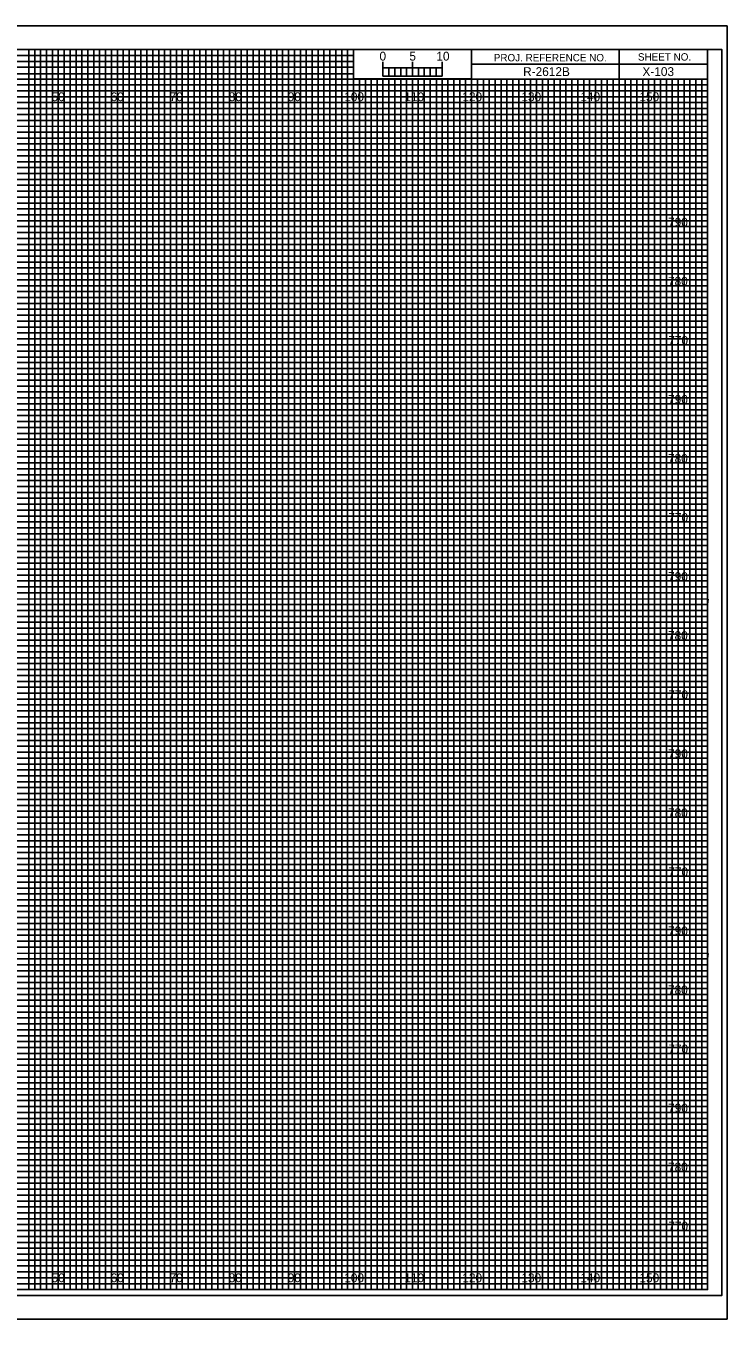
# Model space of a CAD drawing. Extents: x -13 to 323, y -5 to 214.
# Drawn here: x 204.5 to 323.3, y -5 to 214 of the extents above; entities that cross this region are included whole.
import ezdxf

# ---------------------------------------------------------------- set-up
doc = ezdxf.new("R2010")
doc.units = 0
for name, color, linetype in [('Prop XS Bar Scale Labels', 7, 'Continuous'), ('Prop XS Elevation Labels', 7, 'Continuous'), ('Prop XS Offset Labels', 7, 'Continuous'), ('Prop XS Project Number', 7, 'Continuous'), ('Prop XS Sheet Number', 7, 'Continuous'), ('Sheet Cross Section CELL', 7, 'Continuous'), ('Sheet Cross Section Grid Major CELL', 7, 'Continuous'), ('Sheet Cross Section Grid Middle CELL', 7, 'Continuous'), ('Sheet Cross Section Grid Minor 1 CELL', 7, 'Continuous'), ('Sheet Cross Section Grid Minor 2 CELL', 7, 'Continuous'), ('Sheet Cross Section Scale CELL', 7, 'Continuous'), ('Sheet Cutting Line CELL', 7, 'Continuous'), ('Sheet DOT Grid CELL', 7, 'Continuous'), ('Sheet Plot Border Inside CELL', 7, 'Continuous'), ('Sheet Plot Border Outside CELL', 7, 'Continuous')]:
    doc.layers.add(name, color=color, linetype=linetype)

msp = doc.modelspace()

# ---------------------------------------------------------------- linework, layer by layer
at = {"layer": 'Sheet Cross Section CELL'}
for p, q in [((305, 210), (305, 205)), ((305, 205), (305, 210)), ((280, 207.5), (280, 205)), ((320, 207.49), (280, 207.49)), ((280, 205), (320, 205))]:
    msp.add_line(p, q, dxfattribs=at)
for points in [[(320, 210), (0, 210), (0, 0), (320, 0)], [(280, 210), (260, 210), (260, 205.03), (280, 205.03)], [(320, 210), (280, 210), (280, 205), (320, 205)]]:
    msp.add_lwpolyline(points, close=True, dxfattribs=at)
at = {"layer": 'Sheet Cross Section Grid Major CELL'}
for p, q in [((210, 210), (200, 210)), ((210, 0), (210, 210)), ((230, 210), (220, 210)), ((220, 210), (220, 0)), ((230, 0), (230, 210)), ((250, 210), (240, 210)), ((240, 210), (240, 0)), ((250, 0), (250, 210)), ((260, 210), (260, 0)), ((270, 0), (270, 205)), ((290, 205), (280, 205)), ((280, 205), (280, 0)), ((290, 0), (290, 205)), ((310, 205), (300, 205)), ((300, 205), (300, 0)), ((310, 0), (310, 205)), ((220, 0), (210, 0)), ((240, 0), (230, 0)), ((260, 0), (250, 0)), ((280, 0), (270, 0)), ((300, 0), (290, 0)), ((320, 0), (310, 0)), ((320, 0), (320, 0))]:
    msp.add_line(p, q, dxfattribs=at)
for points in [[(0, 200), (320, 200), (320, 190), (0, 190)], [(0, 180), (320, 180), (320, 170), (0, 170)], [(0, 160), (320, 160), (320, 150), (0, 150)], [(0, 140), (320, 140), (320, 130), (0, 130)], [(0, 120), (320, 120), (320, 110), (0, 110)], [(0, 100), (320, 100), (320, 90), (0, 90)], [(0, 80), (320, 80), (320, 70), (0, 70)], [(0, 60), (320, 60), (320, 50), (0, 50)], [(0, 40), (320, 40), (320, 30), (0, 30)], [(0, 20), (320, 20), (320, 10), (0, 10)]]:
    msp.add_lwpolyline(points, dxfattribs=at)
at = {"layer": 'Sheet Cross Section Grid Middle CELL'}
for points in [[(195, 210), (205, 210), (205, 0), (215, 0), (215, 210), (225, 210), (225, 0), (235, 0), (235, 210), (245, 210), (245, 0), (255, 0), (255, 210), (259.93, 210), (260, 210), (260, 205), (264.99, 205), (264.99, 0), (275, 0), (275, 205), (285, 205), (285, 0), (295, 0), (295, 205), (305, 205), (305, 0), (315, 0), (315, 205)], [(0, 205), (275, 205)], [(0, 185), (320, 185), (320, 195), (0, 195)], [(0, 165), (320, 165), (320, 175), (0, 175)], [(0, 145), (320, 145), (320, 155), (0, 155)], [(0, 125), (320, 125), (320, 135), (0, 135)], [(0, 105), (320, 105), (320, 115), (0, 115)], [(0, 85), (320, 85), (320, 95), (0, 95)], [(0, 65), (320, 65), (320, 75), (0, 75)], [(0, 45), (320, 45), (320, 55), (0, 55)], [(0, 25), (320, 25), (320, 35), (0, 35)], [(0, 5), (320, 5), (320, 15), (0, 15)]]:
    msp.add_lwpolyline(points, dxfattribs=at)
at = {"layer": 'Sheet Cross Section Grid Minor 1 CELL'}
for p, q in [((0, 209), (260, 209)), ((260, 209), (260, 207.98)), ((260, 207.98), (0, 207.98)), ((0, 207), (260, 207)), ((260, 205.89), (0, 205.89)), ((260, 207), (260, 205.89)), ((0, 204), (320, 204))]:
    msp.add_line(p, q, dxfattribs=at)
for points in [[(0, 203), (270, 203), (320, 203), (320, 202), (0, 202)], [(0, 201), (320, 201), (320, 199), (0, 199)], [(0, 198), (320, 198), (320, 197), (0, 196.98)], [(0, 196), (320, 196), (320, 194), (0, 194)], [(0, 193), (320, 193), (320, 192), (0, 192)], [(0, 191), (320, 191), (320, 189), (0, 189)], [(0, 188), (320, 188), (320, 187), (0, 187)], [(0, 186), (320, 186), (320, 184), (0, 184)], [(0, 183), (320, 183), (320, 182), (0, 182)], [(0, 181), (320, 181), (320, 179), (0, 179)], [(0, 178), (320, 178), (320, 177), (0, 177)], [(0, 176), (320, 176), (320, 173.95), (320, 173), (320, 172), (0, 172)], [(0, 174), (320, 174), (320, 173), (0, 173)], [(0, 171), (320, 171), (320, 169), (0, 169.03)], [(0, 169.03), (320, 169), (320, 168), (0, 168)], [(0, 167), (320, 167), (320, 166), (0, 166)], [(0, 164), (320, 164), (320, 163), (0, 163)], [(0, 162), (320, 162), (320, 161), (0, 161)], [(-0.07, 158.89), (320, 158.89), (320, 157.88), (-0.07, 157.88)], [(0, 157), (320, 157), (320, 156), (0, 156)], [(0, 154), (320, 154), (320, 153), (0, 153)], [(0, 152), (320, 152), (320, 151), (0, 151)], [(0, 149), (320, 149), (320, 148), (0, 148)], [(0, 147), (320, 147), (320, 146), (0, 146)], [(0, 144), (320, 144), (320, 143), (0, 143)], [(0, 142), (320, 142), (320, 141), (0, 141)], [(0, 139), (320, 139), (319.99, 137.98), (0, 138)], [(0, 137), (320, 137), (320, 136), (0, 136)], [(0, 134), (320, 134), (320, 133), (0, 133)], [(0, 132), (320, 132), (320, 131), (0, 131)], [(0, 129), (320, 129), (320, 128), (0, 128)], [(0, 127), (320, 127), (320, 126), (0, 126)], [(0, 124), (320, 124), (320, 123), (0, 123)], [(0, 122), (320, 122), (320, 121), (0, 121)], [(0, 119), (320, 119), (320, 118), (0, 118)], [(0, 116.99), (320.07, 116.91), (320, 116), (0, 116)], [(0, 114), (320, 114), (320, 113), (0, 113)], [(0, 112), (320, 112), (320, 111), (0, 111)], [(0, 109), (320, 109), (320, 108), (0, 108)], [(0, 107), (320, 107), (320, 106), (0, 106)], [(0, 104), (320, 104), (320, 103), (0, 103)], [(0, 102), (320, 102), (320, 101), (0, 101)], [(0, 99), (320, 99), (320, 98), (0, 98)], [(0, 97), (320, 97), (320, 96), (0, 96)], [(0, 94), (320, 94), (320, 93), (0, 93)], [(0, 92), (320, 92), (320, 91), (0, 91)], [(0, 89), (320, 89), (320, 88), (0, 88)], [(0, 87), (320, 87), (320, 86), (0, 86)], [(0, 84), (320, 84), (320, 83), (0, 83)], [(0, 82), (320, 82), (320, 81), (0, 81)], [(0, 79), (320, 79), (319.99, 77.98), (0, 78)], [(0, 77), (320, 77), (320, 76), (0, 76)], [(0, 74), (320, 74), (320, 73), (0, 73)], [(0, 72), (320, 72), (320, 71), (0, 71)], [(0, 69), (320, 69), (320, 68), (0, 68)], [(0, 67), (320, 67), (320, 66), (0, 66)], [(0, 64), (320, 64), (320, 63), (0, 63)], [(0, 62), (320, 62), (320, 61), (0, 61)], [(0, 59), (320, 59), (320, 58), (0, 58)], [(0, 56.99), (320.07, 56.91), (320, 56), (0, 56)], [(0, 54), (320, 54), (320, 53), (0, 53)], [(0, 52), (320, 52), (320, 51), (0, 51)], [(0, 49), (320, 49), (320, 48), (0, 48)], [(0, 47), (320, 47), (320, 46), (0, 46)], [(0, 44), (320, 44), (320, 43), (0, 43)], [(0, 42), (320, 42), (320, 41), (0, 41)], [(0, 39), (320, 39), (320, 38), (0, 38)], [(0, 37), (320, 37), (320, 36), (0, 36)], [(0, 34), (320, 34), (320, 33), (0, 33)], [(0, 32), (320, 32), (320, 31), (0, 31)], [(0, 29), (320, 29), (320, 28), (0, 28)], [(0, 27), (320, 27), (320, 26), (0, 26)], [(0, 24), (320, 24), (320, 23), (0, 23)], [(0, 22), (320, 22), (320, 21), (0, 21)], [(0, 19), (320, 19), (320, 18), (0, 18)], [(0, 17), (320, 17), (320, 16), (0, 16)], [(0, 14), (320, 14), (320, 13), (0, 13)], [(0, 12), (320, 12), (320, 11), (0, 11)], [(0, 9), (320, 9), (320, 8), (0, 8)], [(0, 7), (320, 7), (320, 6), (0, 6)], [(0, 4), (320, 4), (320, 3), (0, 3)], [(0, 2), (320, 2), (320, 1), (0, 1)]]:
    msp.add_lwpolyline(points, dxfattribs=at)
at = {"layer": 'Sheet Cross Section Grid Minor 2 CELL'}
for p, q in [((267, 205), (266.01, 205)), ((266.01, 205), (266.01, 0)), ((267, 0), (267, 205)), ((269, 205), (268, 205)), ((268, 205), (268, 0)), ((269, 0), (269, 205)), ((266.01, 0), (265, 0)), ((268, 0), (267, 0))]:
    msp.add_line(p, q, dxfattribs=at)
for points in [[(205, 0), (206, 0), (206, 210), (207, 210), (207, 0)], [(207, 0), (208, 0), (208, 210), (209, 210), (209, 0)], [(210, 0), (211, 0), (211, 210), (212, 210), (212, 0)], [(212, 0), (213, 0), (213, 210), (214, 210), (214, 0)], [(215, 0), (216, 0), (216, 210), (217, 210), (217, 0)], [(217, 0), (218, 0), (218, 210), (219, 210), (219, 0)], [(220, 0), (221, 0), (221, 210), (222, 210), (222, 0)], [(222, 0), (223, 0), (223, 210), (224, 210), (224, 0)], [(225, 0), (226, 0), (226, 210), (227, 210), (227, 0)], [(227, 0), (228, 0), (228, 210), (229, 210), (229, 0)], [(230, 0), (231, 0), (231, 210), (232, 210), (232, 0)], [(232, 0), (233, 0), (233, 210), (234, 210), (234, 0)], [(235, 0), (236, 0), (236, 210), (237, 210), (237, 0)], [(237, 0), (238, 0), (238, 210), (239, 210), (239, 0)], [(240, 0), (241, 0), (241, 210), (242, 210), (242, 0)], [(242, 0), (243, 0), (243, 210), (244, 210), (244, 0)], [(245, 0), (246, 0), (246, 210), (247, 210), (247, 0)], [(247, 0), (248, 0), (248, 210), (249, 210), (249, 0)], [(250, 0), (251, 0), (251, 210), (252, 210), (252, 0)], [(252, 0), (253, 0), (253, 210), (254, 210), (254, 0)], [(255, 0), (256, 0), (256, 210), (257, 210), (257, 0)], [(257, 0), (258, 0), (258, 210), (259, 210), (259, 0)], [(260, 0), (261, 0), (261, 205), (262.02, 205), (262.02, 0)], [(262, 0), (263, 0), (263, 205), (263.99, 205), (263.99, 0)], [(270, 0), (270.98, 0), (270.98, 205), (272, 205), (272, 0)], [(272, 0), (273, 0), (273, 205), (274.05, 205), (274.05, 0)], [(275, 0), (276, 0), (276, 205), (277, 205), (277, 0)], [(277, 0), (278, 0), (278, 205), (279, 205), (279, 0)], [(280, 0), (281, 0), (281, 205), (282, 205), (282, 0)], [(282, 0), (283, 0), (283, 205), (284, 205), (284, 0)], [(285, 0), (286, 0), (286, 205), (287, 205), (287, 0)], [(287, 0), (288, 0), (288, 205), (289, 205), (289, 0)], [(290, 0), (291, 0), (291, 205), (292, 205), (292, 0)], [(292, 0), (293, 0), (293, 205), (294, 205), (294, 0)], [(295, 0), (296, 0), (296, 205), (297, 205), (297, 0)], [(297, 0), (298, 0), (298, 205), (299, 205), (299, 0)], [(300, 0), (301, 0), (301, 205), (302, 205), (302, 0)], [(302, 0), (303, 0), (303, 205), (304, 205), (304, 0)], [(305, 0), (306, 0), (306, 205), (307, 205), (307, 0)], [(307, 0), (308, 0), (308, 205), (309, 205), (309, 0)], [(310, 0), (311, 0), (311, 205), (312, 205), (312, 0)], [(312, 0), (313, 0), (313, 205), (314, 205), (314, 0)], [(315, 0), (316, 0), (316, 205), (317, 205), (317, 0)], [(317, 0), (318, 0), (318, 205), (319, 205), (319, 0)]]:
    msp.add_lwpolyline(points, dxfattribs=at)
at = {"layer": 'Sheet Cross Section Scale CELL'}
for p, q in [((265, 205.49), (265, 207.9)), ((265, 206.9), (265, 207.9)), ((270, 205.49), (270, 207.9)), ((275, 205.49), (275, 207.9)), ((275, 206.9), (275, 207.9))]:
    msp.add_line(p, q, dxfattribs=at)
for points in [[(275, 206.9), (265, 206.9), (265, 205.49), (275, 205.49)], [(265, 206.9), (266, 206.9), (266, 205.49), (265, 205.49)], [(267, 206.9), (268, 206.9), (268, 205.49), (267, 205.49)], [(269, 206.9), (270, 206.9), (270, 205.49), (269, 205.49)], [(271, 206.9), (272, 206.9), (272, 205.49), (271, 205.49)], [(273, 206.9), (274, 206.9), (274, 205.49), (273, 205.49)]]:
    msp.add_lwpolyline(points, close=True, dxfattribs=at)
at = {"layer": 'Sheet Cutting Line CELL'}
for p, q in [((323.3, 214), (-13.4, 214)), ((-13.4, -5), (323.3, -5))]:
    msp.add_line(p, q, dxfattribs=at)
at = {"layer": 'Sheet DOT Grid CELL'}
for p, q in [((210, 0), (210, 210)), ((220, 0), (220, 210)), ((230, 0), (230, 210)), ((240, 0), (240, 210)), ((250, 0), (250, 210)), ((260, 0), (260, 204.69)), ((270, 0), (270, 204.69)), ((280, 0), (280, 204.69)), ((290, 0), (290, 204.69)), ((300, 0), (300, 204.69)), ((310, 0), (310, 204.69)), ((0, 200), (320, 200)), ((0, 190), (320, 190)), ((0, 180), (320, 180)), ((0, 170), (320, 170)), ((0, 160), (320, 160)), ((0, 150), (320, 150)), ((0, 140), (320, 140)), ((0, 130), (320, 130)), ((0, 120), (320, 120)), ((0, 110), (320, 110)), ((0, 100), (320, 100)), ((0, 90), (320, 90)), ((0, 80), (320, 80)), ((0, 70), (320, 70)), ((0, 60), (320, 60)), ((0, 50), (320, 50)), ((0, 40), (320, 40)), ((0, 30), (320, 30)), ((0, 20), (320, 20)), ((0, 10), (320, 10))]:
    msp.add_line(p, q, dxfattribs=at)
at = {"layer": 'Sheet Plot Border Inside CELL'}
msp.add_lwpolyline([(-10.8, -1), (322.4, -1), (322.4, 210), (-10.8, 210)], close=True, dxfattribs=at)
at = {"layer": 'Sheet Plot Border Outside CELL'}
msp.add_lwpolyline([(-13.4, -5), (323.3, -5), (323.3, 214), (-13.4, 214)], close=True, dxfattribs=at)

# ---------------------------------------------------------------- texts
at = {"layer": 'Prop XS Bar Scale Labels'}
for s, p in [('5', (269.47, 208.12)), ('10', (274.04, 208.12))]:
    msp.add_text(s, height=1.5, dxfattribs=at).set_placement(p)
at = {"layer": 'Prop XS Elevation Labels'}
for s, p in [('790', (313.3, 180)), ('780', (313.28, 170)), ('770', (313.33, 160)), ('790', (313.3, 150)), ('780', (313.28, 140)), ('770', (313.33, 130)), ('790', (313.3, 120)), ('780', (313.28, 110)), ('770', (313.33, 100)), ('790', (313.3, 90)), ('780', (313.28, 80)), ('770', (313.33, 70)), ('790', (313.3, 60)), ('780', (313.28, 50)), ('770', (313.33, 40)), ('790', (313.3, 30)), ('780', (313.28, 20)), ('770', (313.33, 10))]:
    msp.add_text(s, height=1.5, dxfattribs=at).set_placement(p)
at = {"layer": 'Prop XS Offset Labels'}
for s, p in [('50', (208.86, 201.25)), ('60', (218.86, 201.25)), ('70', (228.86, 201.25)), ('80', (238.86, 201.25)), ('90', (248.86, 201.25)), ('100', (258.44, 201.25)), ('110', (268.62, 201.25)), ('120', (278.44, 201.25)), ('130', (288.44, 201.25)), ('140', (298.44, 201.25)), ('150', (308.44, 201.25)), ('50', (208.86, 1.25)), ('60', (218.86, 1.25)), ('70', (228.86, 1.25)), ('80', (238.86, 1.25)), ('90', (248.86, 1.25)), ('100', (258.44, 1.25)), ('110', (268.62, 1.25)), ('120', (278.44, 1.25)), ('130', (288.44, 1.25)), ('140', (298.44, 1.25)), ('150', (308.44, 1.25))]:
    msp.add_text(s, height=1.5, dxfattribs=at).set_placement(p)
at = {"layer": 'Prop XS Project Number'}
msp.add_text('R-2612B', height=1.5, dxfattribs=at).set_placement((288.74, 205.5))
at = {"layer": 'Prop XS Sheet Number'}
msp.add_text('X-103', height=1.5, dxfattribs=at).set_placement((308.95, 205.5))
at = {"layer": 'Sheet Cross Section CELL'}
for s, p in [('PROJ. REFERENCE NO.', (283.77, 207.99)), ('SHEET NO.', (308.19, 208.12))]:
    msp.add_text(s, height=1.25, dxfattribs=at).set_placement(p)
at = {"layer": 'Sheet Cross Section Scale CELL'}
msp.add_text('0', height=1.5, dxfattribs=at).set_placement((264.41, 208.12))

doc.saveas('drawing.dxf')
